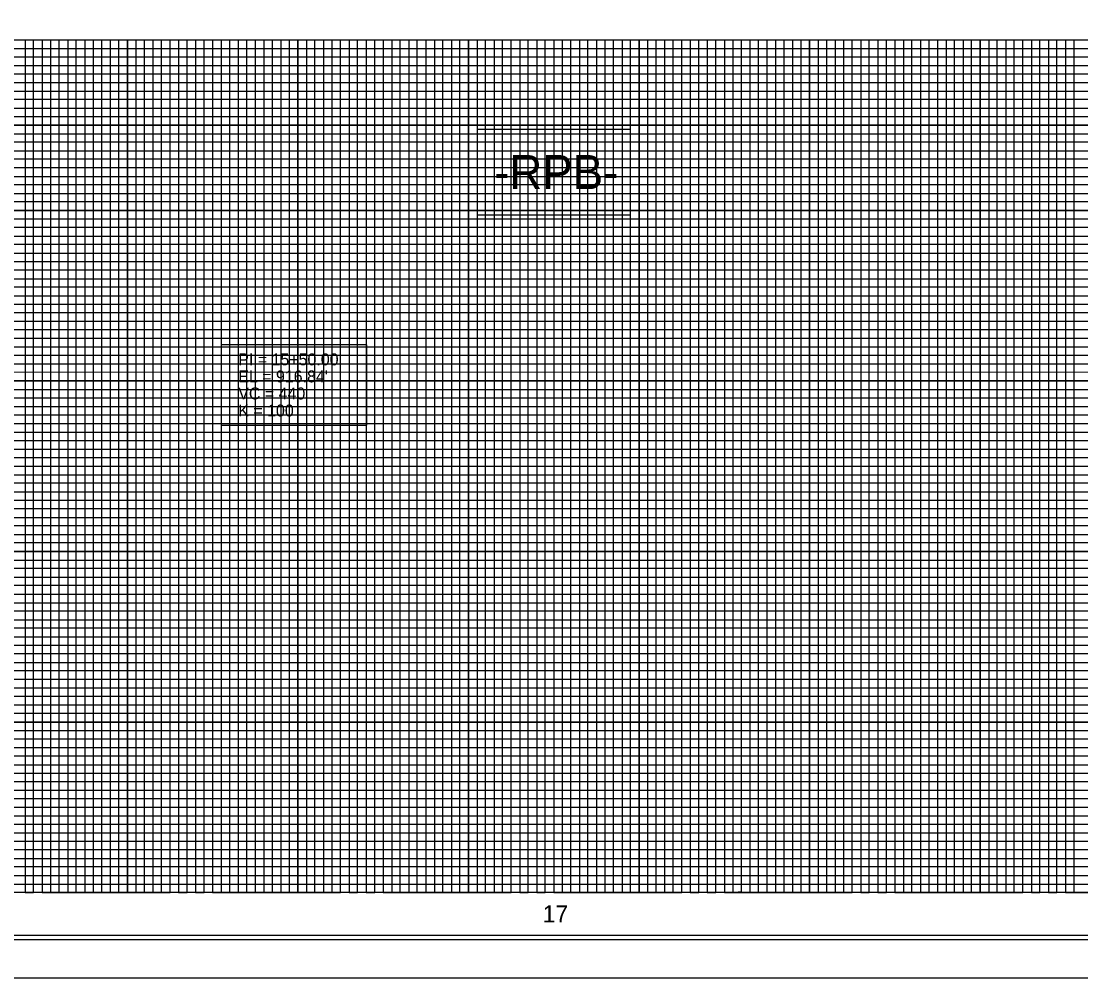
# Model space of a CAD drawing. Extents: x 1648862 to 1650715, y 820691 to 821791.
# Drawn here: x 1649467 to 1650088, y 820691 to 821252 of the extents above; entities that cross this region are included whole.
import ezdxf

# ---------------------------------------------------------------- set-up
doc = ezdxf.new("R2010")
doc.units = 0
for name, color, linetype in [('Exist Vertical Profile Horizontal Axis Label Major', 7, 'Continuous'), ('Prop Grid Mask', 7, 'Continuous'), ('Prop Vertical Profile Curve Label', 7, 'Continuous'), ('Prop VPI Label', 7, 'Continuous'), ('Sheet Cutting Line CELL', 7, 'Continuous'), ('Sheet DOT Grid CELL', 7, 'Continuous'), ('Sheet Layout Profile Border Port 2', 7, 'Continuous'), ('Sheet Plot Border Inside CELL', 7, 'Continuous'), ('Sheet Plot Border Outside CELL', 7, 'Continuous'), ('Sheet Profile CELL', 7, 'Continuous'), ('Sheet Profile Grid Major CELL', 7, 'Continuous'), ('Sheet Profile Grid Middle CELL', 7, 'Continuous'), ('Sheet Profile Grid Minor CELL', 7, 'Continuous')]:
    doc.layers.add(name, color=color, linetype=linetype)

msp = doc.modelspace()

# ---------------------------------------------------------------- linework, layer by layer
at = {"layer": 'Prop Grid Mask'}
for points in [[(1649734.28, 821188.52), (1649734.28, 821138.52), (1649824.28, 821138.52), (1649824.28, 821188.52)], [(1649584.28, 821062.2), (1649584.28, 821015.2), (1649669.75, 821015.2), (1649669.75, 821062.2)]]:
    msp.add_lwpolyline(points, close=True, dxfattribs=at)
at = {"layer": 'Sheet Cutting Line CELL'}
msp.add_line((1648862.28, 820691.02), (1650546.28, 820691.02), dxfattribs=at)
at = {"layer": 'Sheet DOT Grid CELL'}
for p, q in [((1649029.28, 821241.02), (1650529.17, 821241.02)), ((1649479.28, 821241.02), (1649479.28, 820741.02)), ((1649529.28, 821241.02), (1649529.28, 820741.02)), ((1649579.28, 821241.02), (1649579.28, 820741.02)), ((1649629.28, 821241.02), (1649629.28, 820741.02)), ((1649679.28, 821241.02), (1649679.28, 820741.02)), ((1649729.28, 821241.02), (1649729.28, 820741.02)), ((1649779.28, 821241.02), (1649779.28, 820741.02)), ((1649829.28, 821241.02), (1649829.28, 820741.02)), ((1649879.28, 821241.02), (1649879.28, 820741.02)), ((1649929.28, 821241.02), (1649929.28, 820741.02)), ((1649979.28, 821241.02), (1649979.28, 820741.02)), ((1650029.28, 821241.02), (1650029.28, 820741.02)), ((1650079.28, 821241.02), (1650079.28, 820741.02)), ((1649029.28, 821191.02), (1650529.17, 821191.02)), ((1649029.28, 821141.02), (1650529.17, 821141.02)), ((1649029.28, 821091.02), (1650529.17, 821091.02)), ((1649029.28, 821041.02), (1650529.17, 821041.02)), ((1649029.28, 820991.02), (1650529.17, 820991.02)), ((1649029.28, 820941.02), (1650529.17, 820941.02)), ((1649029.28, 820891.02), (1650529.17, 820891.02)), ((1649029.28, 820841.02), (1650529.17, 820841.02)), ((1649029.28, 820791.02), (1650529.17, 820791.02))]:
    msp.add_line(p, q, dxfattribs=at)
at = {"layer": 'Sheet Layout Profile Border Port 2'}
msp.add_lwpolyline([(1649079.28, 821241.02), (1650479.28, 821241.02), (1650479.28, 820741.02), (1649079.28, 820741.02)], close=True, dxfattribs=at)
at = {"layer": 'Sheet Plot Border Inside CELL'}
msp.add_lwpolyline([(1648875.28, 820713.47), (1650541.78, 820713.47), (1650541.78, 821768.57), (1648875.28, 821768.57)], close=True, dxfattribs=at)
at = {"layer": 'Sheet Plot Border Outside CELL'}
msp.add_lwpolyline([(1648862.28, 820691.02), (1650546.28, 820691.02), (1650546.28, 821791.02), (1648862.28, 821791.02)], close=True, dxfattribs=at)
at = {"layer": 'Sheet Profile CELL'}
for p, q in [((1649029.28, 821241.02), (1650529.28, 821241.02)), ((1650529.28, 820741.02), (1649029.28, 820741.02)), ((1649029.28, 820716.02), (1650529.28, 820716.02))]:
    msp.add_line(p, q, dxfattribs=at)
msp.add_lwpolyline([(1650529.28, 821766.02), (1649029.28, 821766.02), (1649029.28, 820716.02), (1650529.28, 820716.02)], close=True, dxfattribs=at)
at = {"layer": 'Sheet Profile Grid Major CELL'}
for p, q in [((1649529.28, 821241.02), (1649579.28, 821241.02)), ((1649629.28, 821241.02), (1649679.28, 821241.02)), ((1649729.28, 821241.02), (1649779.28, 821241.02)), ((1649829.28, 821241.02), (1649879.28, 821241.02)), ((1649929.28, 821241.02), (1649979.28, 821241.02)), ((1650029.28, 821241.02), (1650079.28, 821241.02))]:
    msp.add_line(p, q, dxfattribs=at)
for points in [[(1649429.28, 821241.02), (1649479.28, 821241.02), (1649479.28, 820741.02), (1649529.28, 820741.02), (1649529.28, 821241.02), (1649579.28, 821241.02), (1649579.28, 820741.02), (1649629.28, 820741.02), (1649629.28, 821241.02), (1649679.28, 821241.02), (1649679.28, 820741.02), (1649729.28, 820741.02), (1649729.28, 821241.02), (1649779.28, 821241.02), (1649779.28, 820741.02), (1649829.28, 820741.02), (1649829.28, 821241.02), (1649879.28, 821241.02), (1649879.28, 820741.02), (1649929.28, 820741.02), (1649929.28, 821241.02), (1649979.28, 821241.02), (1649979.28, 820741.02), (1650029.28, 820741.02), (1650029.28, 821241.02), (1650079.28, 821241.02), (1650079.28, 820741.02), (1650129.28, 820741.02)], [(1650529.28, 821191.02), (1649029.28, 821191.02)], [(1650529.28, 821141.02), (1649029.28, 821141.02), (1649029.28, 821091.02), (1650529.28, 821091.02)], [(1650529.28, 821041.02), (1649029.28, 821041.02), (1649029.28, 820991.02), (1650529.28, 820991.02)], [(1650529.28, 820941.02), (1649029.28, 820941.02), (1649029.28, 820891.02), (1650529.28, 820891.02)], [(1650529.28, 820841.02), (1649029.28, 820841.02), (1649029.28, 820841.02), (1649029.28, 820791.02), (1650529.28, 820791.02)], [(1650529.28, 820741.02), (1649029.28, 820741.02)]]:
    msp.add_lwpolyline(points, dxfattribs=at)
at = {"layer": 'Sheet Profile Grid Middle CELL'}
for points in [[(1649454.28, 821241.02), (1649504.28, 821241.02), (1649504.28, 820741.02), (1649554.28, 820741.02), (1649554.28, 821241.02), (1649604.28, 821241.02), (1649604.28, 820741.02), (1649654.28, 820741.02), (1649654.28, 820741.02), (1649654.28, 821241.02), (1649704.28, 821241.02), (1649704.28, 820741.02), (1649754.28, 820741.02), (1649754.28, 821241.02), (1649804.28, 821241.02), (1649804.28, 820741.02), (1649854.28, 820741.02), (1649854.28, 821241.02), (1649904.28, 821241.02), (1649904.28, 820741.02), (1649954.28, 820741.02), (1649954.28, 821241.02), (1650004.28, 821241.02), (1650004.28, 820741.02), (1650054.28, 820741.02), (1650054.28, 821241.02), (1650104.28, 821241.02)], [(1649029.28, 821216.02), (1650529.28, 821216.02)], [(1650529.28, 821166.02), (1649029.28, 821166.02), (1649029.28, 821116.02), (1650529.28, 821116.02)], [(1650529.28, 821066.02), (1649029.28, 821066.02), (1649029.28, 821016.02), (1650529.28, 821016.02)], [(1650529.28, 820966.02), (1649029.28, 820966.02), (1649029.28, 820916.02), (1650529.28, 820916.02)], [(1650529.28, 820866.02), (1649029.28, 820866.02), (1649029.28, 820816.02), (1650529.28, 820816.02)], [(1650529.28, 820766.02), (1649029.28, 820766.02)]]:
    msp.add_lwpolyline(points, dxfattribs=at)
at = {"layer": 'Sheet Profile Grid Minor CELL'}
for p, q in [((1649079.28, 821236.02), (1650479.28, 821236.02)), ((1650479.28, 821231.02), (1649079.28, 821231.02)), ((1649079.28, 821226.02), (1650479.28, 821226.02)), ((1650479.28, 821221.02), (1649079.28, 821221.02)), ((1649079.28, 821211.02), (1650479.28, 821211.02)), ((1650479.28, 821206.02), (1649079.28, 821206.02)), ((1649079.28, 821201.02), (1650479.28, 821201.02)), ((1650479.28, 821196.02), (1649079.28, 821196.02)), ((1649079.28, 821186.02), (1650479.28, 821186.02)), ((1650479.28, 821181.02), (1649079.28, 821181.02)), ((1649079.28, 821176.02), (1650479.28, 821176.02)), ((1650479.28, 821171.02), (1649079.28, 821171.02)), ((1649079.28, 821161.02), (1650479.28, 821161.02)), ((1650479.28, 821156.02), (1649079.28, 821156.02)), ((1649079.28, 821151.02), (1650479.28, 821151.02)), ((1650479.28, 821146.02), (1649079.28, 821146.02)), ((1649079.28, 821136.02), (1650479.28, 821136.02)), ((1650479.28, 821131.02), (1649079.28, 821131.02)), ((1649079.28, 821126.02), (1650479.28, 821126.02)), ((1650479.28, 821121.02), (1649079.28, 821121.02)), ((1649079.28, 821111.02), (1650479.28, 821111.02)), ((1650479.28, 821106.02), (1649079.28, 821106.02)), ((1649079.28, 821101.02), (1650479.28, 821101.02)), ((1650479.28, 821096.02), (1649079.28, 821096.02)), ((1649079.28, 821086.02), (1650479.28, 821086.02)), ((1650479.28, 821081.02), (1649079.28, 821081.02)), ((1649079.28, 821076.02), (1650479.28, 821076.02)), ((1650479.28, 821071.02), (1649079.28, 821071.02)), ((1649079.28, 821061.02), (1650479.28, 821061.02)), ((1650479.28, 821056.02), (1649079.28, 821056.02)), ((1649079.28, 821051.02), (1650479.28, 821051.02)), ((1650479.28, 821046.02), (1649079.28, 821046.17)), ((1649079.28, 821036.02), (1650479.28, 821036.02)), ((1650479.28, 821031.02), (1649079.28, 821031.02)), ((1649079.28, 821026.02), (1650479.28, 821026.02)), ((1650479.28, 821021.02), (1649079.28, 821021.02)), ((1649079.28, 821011.02), (1650479.28, 821011.02)), ((1650479.28, 821006.02), (1649079.28, 821006.02)), ((1649079.28, 821001.02), (1650479.28, 821001.02)), ((1650479.28, 820996.02), (1649079.28, 820996.02)), ((1649079.28, 820986.02), (1650479.28, 820986.02)), ((1650479.28, 820981.02), (1649079.28, 820981.02)), ((1649079.28, 820976.02), (1650479.28, 820976.02)), ((1650479.28, 820971.02), (1649079.28, 820971.02)), ((1649079.28, 820961.02), (1650479.28, 820961.02)), ((1650479.28, 820956.02), (1649079.28, 820956.02)), ((1649079.28, 820951.02), (1650479.28, 820951.02)), ((1650479.28, 820946.02), (1649079.28, 820946.02)), ((1649079.28, 820936.02), (1650479.28, 820936.02)), ((1650479.28, 820931.02), (1649079.28, 820931.02)), ((1649079.28, 820926.02), (1650479.28, 820926.02)), ((1650479.28, 820921.02), (1649079.28, 820921.02)), ((1649079.28, 820911.02), (1650479.28, 820911.02)), ((1650479.28, 820906.02), (1649079.28, 820906.02)), ((1649079.28, 820901.02), (1650479.28, 820901.02)), ((1650479.28, 820896.02), (1649079.28, 820896.02)), ((1649079.28, 820886.02), (1650479.28, 820886.02)), ((1650479.28, 820881.02), (1649079.28, 820881.02)), ((1649079.28, 820876.02), (1650479.28, 820876.02)), ((1650479.28, 820871.02), (1649079.28, 820871.02)), ((1649079.28, 820861.02), (1650479.28, 820861.02)), ((1650479.28, 820856.02), (1649079.28, 820856.02)), ((1649079.28, 820851.02), (1650479.28, 820851.02)), ((1650479.28, 820846.02), (1649079.28, 820846.02)), ((1649079.28, 820836.02), (1650479.28, 820836.02)), ((1650479.28, 820831.02), (1649079.28, 820831.02)), ((1649079.28, 820826.02), (1650479.28, 820826.02)), ((1650479.28, 820821.02), (1649079.28, 820821.02)), ((1649079.28, 820811.02), (1650479.28, 820811.02)), ((1650479.28, 820806.02), (1649079.28, 820806.02)), ((1649079.28, 820801.02), (1650479.28, 820801.02)), ((1650479.28, 820796.02), (1649079.28, 820796.02)), ((1649079.28, 820786.02), (1650479.28, 820786.02)), ((1650479.28, 820781.02), (1649079.28, 820781.02)), ((1649079.28, 820776.02), (1650479.28, 820776.02)), ((1650479.28, 820771.02), (1649079.28, 820771.02)), ((1649079.28, 820761.02), (1650479.28, 820761.02)), ((1650479.28, 820756.02), (1649079.28, 820756.02)), ((1649079.28, 820751.02), (1650479.28, 820751.02)), ((1649079.28, 820746.02), (1650479.28, 820746.02))]:
    msp.add_line(p, q, dxfattribs=at)
for points in [[(1649464.28, 821241.02), (1649469.28, 821241.02), (1649469.28, 820741.02), (1649474.28, 820741.02), (1649474.28, 821241.02), (1649484.28, 821241.02), (1649484.28, 820741.02), (1649489.28, 820741.02), (1649489.28, 821241.02), (1649494.28, 821241.02), (1649494.28, 820741.02), (1649499.28, 820741.02), (1649499.28, 821241.02), (1649509.28, 821241.02), (1649509.28, 820741.02), (1649514.28, 820741.02), (1649514.28, 821241.02), (1649519.28, 821241.02), (1649519.28, 820741.02), (1649524.28, 820741.02), (1649524.28, 821241.02), (1649534.28, 821241.02), (1649534.28, 820741.02), (1649539.28, 820741.02), (1649539.28, 821241.02), (1649544.28, 821241.02), (1649544.28, 820741.02), (1649549.28, 820741.02), (1649549.28, 821241.02), (1649559.28, 821241.02), (1649559.28, 820741.02), (1649564.28, 820741.02), (1649564.28, 821241.02), (1649569.28, 821241.02), (1649569.28, 820741.02), (1649574.28, 820741.02), (1649574.28, 821241.02), (1649584.28, 821241.02), (1649584.28, 820741.02), (1649589.28, 820741.02), (1649589.28, 821241.02), (1649594.28, 821241.02), (1649594.28, 820741.02), (1649599.28, 820741.02), (1649599.28, 821241.02), (1649609.28, 821241.02)], [(1649609.28, 821241.02), (1649609.28, 820741.02), (1649614.28, 820741.02), (1649614.28, 821241.02), (1649619.28, 821241.02), (1649619.28, 820741.02), (1649624.28, 820741.02), (1649624.28, 821241.02), (1649634.28, 821241.02), (1649634.28, 820741.02), (1649639.28, 820741.02), (1649639.28, 821241.02), (1649644.28, 821241.02), (1649644.28, 820741.02), (1649649.28, 820741.02), (1649649.28, 821241.02), (1649659.28, 821241.02), (1649659.28, 820741.02), (1649664.28, 820741.02), (1649664.28, 821241.02), (1649669.28, 821241.02), (1649669.28, 820741.02), (1649674.28, 820741.02), (1649674.28, 821241.02), (1649684.28, 821241.02), (1649684.28, 820741.02), (1649689.28, 820741.02), (1649689.28, 821241.02), (1649694.28, 821241.02), (1649694.28, 820741.02), (1649699.28, 820741.02), (1649699.28, 821241.02), (1649709.28, 821241.02), (1649709.28, 820741.02), (1649714.28, 820741.02), (1649714.28, 821241.02), (1649719.28, 821241.02), (1649719.28, 820741.02), (1649724.28, 820741.02), (1649724.28, 821241.02), (1649734.28, 821241.02), (1649734.28, 820741.02), (1649734.28, 820741.02), (1649739.28, 820741.02), (1649739.28, 821241.02), (1649744.28, 821241.02), (1649744.28, 820741.02), (1649749.28, 820741.02), (1649749.28, 821241.02), (1649759.28, 821241.02), (1649759.28, 820741.02), (1649764.28, 820741.02), (1649764.28, 821241.02), (1649769.28, 821241.02), (1649769.28, 820741.02), (1649774.28, 820741.02), (1649774.28, 821241.02), (1649784.28, 821241.02), (1649784.28, 820741.02), (1649789.28, 820741.02), (1649789.28, 821241.02), (1649794.28, 821241.02), (1649794.28, 820741.02), (1649799.28, 820741.02), (1649799.28, 821241.02), (1649809.28, 821241.02), (1649809.28, 820741.02), (1649814.28, 820741.02), (1649814.28, 821241.02), (1649819.28, 821241.02), (1649819.28, 820741.02), (1649824.28, 820741.02), (1649824.28, 821241.02), (1649834.28, 821241.02), (1649834.28, 820741.02), (1649839.28, 820741.02), (1649839.28, 821241.02), (1649844.28, 821241.02), (1649844.28, 820741.02), (1649849.28, 820741.02), (1649849.28, 821241.02), (1649859.28, 821241.02), (1649859.28, 820741.02), (1649864.28, 820741.02), (1649864.28, 821241.02), (1649869.28, 821241.02), (1649869.28, 820741.02), (1649874.28, 820741.02), (1649874.28, 821241.02), (1649884.28, 821241.02), (1649884.28, 820741.02), (1649888.98, 820741.57), (1649889.28, 820741.02), (1649889.28, 821241.02), (1649894.28, 821241.02), (1649894.28, 820741.02), (1649899.28, 820741.02), (1649899.28, 821241.02), (1649909.28, 821241.02), (1649909.28, 820741.02), (1649914.28, 820741.02)], [(1649914.28, 820741.02), (1649914.28, 821241.02), (1649919.28, 821241.02), (1649919.28, 820741.02), (1649924.28, 820741.02), (1649924.28, 821241.02), (1649934.28, 821241.02), (1649934.28, 820741.02), (1649939.28, 820741.02), (1649939.28, 821241.02), (1649944.28, 821241.02), (1649944.28, 820741.02), (1649949.28, 820741.02), (1649949.28, 821241.02), (1649959.28, 821241.02), (1649959.28, 820741.02), (1649964.28, 820741.02), (1649964.28, 821241.02), (1649969.28, 821241.02), (1649969.28, 820741.02), (1649974.28, 820741.02), (1649974.28, 821241.02), (1649984.28, 821241.02), (1649984.28, 820741.02), (1649989.28, 820741.02), (1649989.28, 821241.02), (1649994.28, 821241.02), (1649994.28, 820741.02), (1649999.28, 820741.02), (1649999.28, 821241.02), (1650009.28, 821241.02), (1650009.28, 820741.02), (1650014.28, 820741.02), (1650014.28, 821241.02), (1650019.28, 821241.02), (1650019.28, 820741.02), (1650024.28, 820741.02), (1650024.28, 821241.02), (1650034.28, 821241.02), (1650034.28, 820741.02), (1650039.28, 820741.02), (1650039.28, 821241.02), (1650044.28, 821241.02), (1650044.28, 820741.02), (1650049.28, 820741.02), (1650049.28, 821241.02), (1650059.28, 821241.02), (1650059.28, 820741.02), (1650064.28, 820741.02), (1650064.28, 821241.02), (1650069.28, 821241.02), (1650069.28, 820741.02), (1650074.28, 820741.02), (1650074.28, 821241.02), (1650084.28, 821241.02), (1650084.28, 820741.02), (1650089.28, 820741.02)]]:
    msp.add_lwpolyline(points, dxfattribs=at)

# ---------------------------------------------------------------- texts
at = {"layer": 'Exist Vertical Profile Horizontal Axis Label Major'}
for s, height, p in [('-RPB-', 20, (1649744.34, 821153.52)), ('17', 10, (1649772.82, 820723.52))]:
    msp.add_text(s, height=height, dxfattribs=at).set_placement(p)
at = {"layer": 'Prop Vertical Profile Curve Label'}
for s, p in [("VC = 440'", (1649594.28, 821030.2)), ('K = 100', (1649594.28, 821020.2))]:
    msp.add_text(s, height=7, dxfattribs=at).set_placement(p)
at = {"layer": 'Prop VPI Label'}
for s, p in [('PI = 15+50.00', (1649594.28, 821050.2)), ("EL = 916.84'", (1649594.28, 821040.2))]:
    msp.add_text(s, height=7, dxfattribs=at).set_placement(p)

doc.saveas('drawing.dxf')
